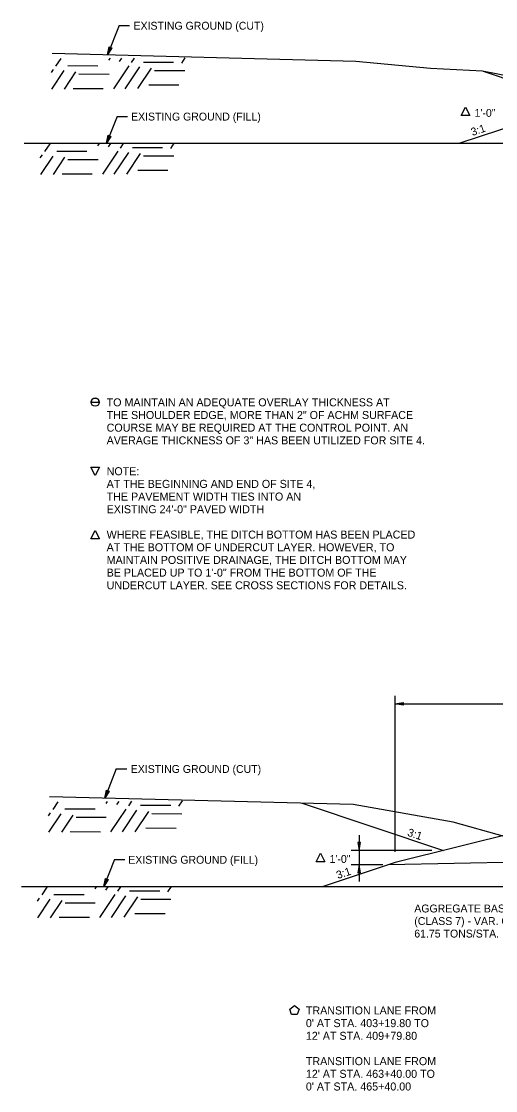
# Model space of a CAD drawing. Extents: x 1398565 to 1398920, y 1968324 to 1968581.
# Drawn here: x 1398765.9 to 1398801.5, y 1968324.3 to 1968404.5 of the extents above; entities that cross this region are included whole.
import ezdxf

# ---------------------------------------------------------------- set-up
doc = ezdxf.new("R2010")
doc.units = 0
for name, color, linetype in [('10', 7, 'Continuous'), ('19', 7, 'Continuous'), ('42', 7, 'Continuous'), ('9', 7, 'Continuous'), ('Default', 7, 'Continuous')]:
    doc.layers.add(name, color=color, linetype=linetype)

msp = doc.modelspace()

# ---------------------------------------------------------------- linework, layer by layer
at = {"layer": '10'}
msp.add_line((1398771.175, 1968375.948), (1398771.786, 1968375.948), dxfattribs=at)
for points in [[(1398799.247, 1968398.068), (1398799.568, 1968397.427), (1398798.927, 1968397.427)], [(1398771.163, 1968371.09), (1398771.804, 1968371.09), (1398771.484, 1968370.448)], [(1398771.484, 1968366.34), (1398771.804, 1968365.698), (1398771.163, 1968365.698)], [(1398788.375, 1968342.144), (1398788.695, 1968341.503), (1398788.054, 1968341.503)], [(1398786.069, 1968330.465), (1398786.418, 1968330.719), (1398786.768, 1968330.465), (1398786.634, 1968330.054), (1398786.202, 1968330.054)]]:
    msp.add_lwpolyline(points, close=True, dxfattribs=at)
msp.add_circle((1398771.48, 1968375.948), 0.306, dxfattribs=at)
msp.add_arc((1398771.48, 1968375.948), 0.306, 0, 180, dxfattribs=at)
at = {"layer": '19'}
for p, q in [((1398773.27, 1968404.183), (1398772.414, 1968401.981)), ((1398773.27, 1968404.183), (1398774.053, 1968404.183)), ((1398772.414, 1968401.981), (1398772.534, 1968402.578)), ((1398772.729, 1968402.502), (1398772.414, 1968401.981)), ((1398772.458, 1968402.135), (1398772.585, 1968402.558)), ((1398772.683, 1968402.52), (1398772.486, 1968402.125)), ((1398772.534, 1968402.578), (1398772.729, 1968402.502)), ((1398800.557, 1968400.762), (1398808.028, 1968398.272)), ((1398806.176, 1968397.808), (1398798.814, 1968395.354)), ((1398773.125, 1968397.374), (1398772.339, 1968395.354)), ((1398773.125, 1968397.374), (1398773.907, 1968397.374)), ((1398772.339, 1968395.354), (1398772.459, 1968395.952)), ((1398772.655, 1968395.876), (1398772.339, 1968395.354)), ((1398772.383, 1968395.509), (1398772.51, 1968395.932)), ((1398772.608, 1968395.894), (1398772.411, 1968395.498)), ((1398772.459, 1968395.952), (1398772.655, 1968395.876)), ((1398793.969, 1968342.234), (1398793.969, 1968353.935)), ((1398793.969, 1968353.335), (1398794.569, 1968353.44)), ((1398793.969, 1968353.335), (1398817.969, 1968353.335)), ((1398794.569, 1968353.23), (1398793.969, 1968353.335)), ((1398794.129, 1968353.35), (1398794.569, 1968353.385)), ((1398794.569, 1968353.28), (1398794.129, 1968353.32)), ((1398794.569, 1968353.44), (1398794.569, 1968353.23)), ((1398773.064, 1968348.472), (1398772.207, 1968346.271)), ((1398773.064, 1968348.472), (1398773.846, 1968348.472)), ((1398772.207, 1968346.271), (1398772.327, 1968346.868)), ((1398772.523, 1968346.792), (1398772.207, 1968346.271)), ((1398772.251, 1968346.425), (1398772.378, 1968346.848)), ((1398772.476, 1968346.81), (1398772.279, 1968346.414)), ((1398772.327, 1968346.868), (1398772.523, 1968346.792)), ((1398786.991, 1968345.885), (1398797.601, 1968342.348)), ((1398811.969, 1968345.94), (1398793.969, 1968341.44)), ((1398791.264, 1968343.506), (1398791.264, 1968342.23)), ((1398791.369, 1968342.948), (1398791.159, 1968342.948)), ((1398791.159, 1968342.948), (1398791.264, 1968342.348)), ((1398791.214, 1968342.948), (1398791.249, 1968342.508)), ((1398791.264, 1968342.348), (1398791.369, 1968342.948)), ((1398791.279, 1968342.508), (1398791.319, 1968342.948)), ((1398842.969, 1968342.264), (1398793.472, 1968341.274)), ((1398772.918, 1968341.664), (1398772.133, 1968339.644)), ((1398772.918, 1968341.664), (1398773.701, 1968341.664)), ((1398791.264, 1968342.23), (1398791.264, 1968340.024)), ((1398793.969, 1968341.44), (1398788.582, 1968339.644)), ((1398791.264, 1968341.274), (1398791.159, 1968340.674)), ((1398791.159, 1968340.674), (1398791.369, 1968340.674)), ((1398791.249, 1968341.114), (1398791.214, 1968340.674)), ((1398791.369, 1968340.674), (1398791.264, 1968341.274)), ((1398791.319, 1968340.674), (1398791.279, 1968341.114)), ((1398772.133, 1968339.644), (1398772.252, 1968340.241)), ((1398772.448, 1968340.165), (1398772.133, 1968339.644)), ((1398772.177, 1968339.799), (1398772.304, 1968340.222)), ((1398772.401, 1968340.183), (1398772.205, 1968339.788)), ((1398772.252, 1968340.241), (1398772.448, 1968340.165))]:
    msp.add_line(p, q, dxfattribs=at)
at = {"layer": '42'}
for points in [[(1398766.153, 1968395.354), (1398812.649, 1968395.354), (1398837.176, 1968401.464), (1398843.176, 1968401.704)], [(1398822.902, 1968397.908), (1398802.82, 1968400.302), (1398800.522, 1968400.764), (1398796.614, 1968400.956), (1398791.017, 1968401.495), (1398768.256, 1968402.089)], [(1398825.029, 1968342.779), (1398805.225, 1968342.765), (1398802.252, 1968343.377), (1398798.325, 1968344.462), (1398790.81, 1968345.785), (1398768.049, 1968346.379)], [(1398765.947, 1968339.644), (1398812.443, 1968339.644), (1398836.969, 1968345.753), (1398842.969, 1968345.993)]]:
    msp.add_lwpolyline(points, dxfattribs=at)
at = {"layer": '9'}
for p, q in [((1398768.53, 1968401.133), (1398768.919, 1968401.716)), ((1398772.514, 1968401.582), (1398772.617, 1968401.737)), ((1398773.312, 1968401.494), (1398773.477, 1968401.742)), ((1398774.202, 1968401.406), (1398774.429, 1968401.747)), ((1398777.966, 1968401.372), (1398778.23, 1968401.768)), ((1398768.193, 1968400.661), (1398768.346, 1968400.891)), ((1398768.221, 1968399.418), (1398769.144, 1968400.803)), ((1398769.42, 1968401.176), (1398771.682, 1968401.17)), ((1398772.871, 1968399.444), (1398774.018, 1968401.164)), ((1398773.731, 1968399.449), (1398774.816, 1968401.076)), ((1398774.684, 1968399.454), (1398775.706, 1968400.988)), ((1398775.092, 1968401.448), (1398777.354, 1968401.443)), ((1398775.93, 1968400.822), (1398778.192, 1968400.816)), ((1398769.173, 1968399.423), (1398770.035, 1968400.715)), ((1398770.258, 1968400.55), (1398772.52, 1968400.544)), ((1398769.819, 1968399.471), (1398772.081, 1968399.465)), ((1398775.491, 1968399.744), (1398777.753, 1968399.738)), ((1398767.705, 1968394.728), (1398768.093, 1968395.311)), ((1398771.688, 1968395.177), (1398771.791, 1968395.331)), ((1398772.486, 1968395.089), (1398772.651, 1968395.336)), ((1398773.377, 1968395.001), (1398773.604, 1968395.341)), ((1398777.14, 1968394.966), (1398777.405, 1968395.363)), ((1398767.367, 1968394.255), (1398767.521, 1968394.486)), ((1398767.395, 1968393.012), (1398768.318, 1968394.398)), ((1398768.594, 1968394.77), (1398770.856, 1968394.764)), ((1398772.046, 1968393.038), (1398773.192, 1968394.759)), ((1398772.906, 1968393.043), (1398773.99, 1968394.67)), ((1398773.858, 1968393.049), (1398774.881, 1968394.583)), ((1398774.266, 1968395.043), (1398776.528, 1968395.037)), ((1398775.104, 1968394.417), (1398777.366, 1968394.411)), ((1398768.347, 1968393.018), (1398769.209, 1968394.31)), ((1398769.432, 1968394.144), (1398771.694, 1968394.138)), ((1398768.993, 1968393.066), (1398771.255, 1968393.06)), ((1398774.665, 1968393.339), (1398776.927, 1968393.333)), ((1398768.324, 1968345.423), (1398768.712, 1968346.006)), ((1398772.308, 1968345.872), (1398772.41, 1968346.027)), ((1398773.105, 1968345.784), (1398773.27, 1968346.031)), ((1398773.996, 1968345.696), (1398774.223, 1968346.037)), ((1398774.885, 1968345.738), (1398777.147, 1968345.732)), ((1398777.76, 1968345.662), (1398778.024, 1968346.058)), ((1398767.986, 1968344.95), (1398768.14, 1968345.181)), ((1398768.014, 1968343.708), (1398768.938, 1968345.093)), ((1398768.967, 1968343.713), (1398769.828, 1968345.005)), ((1398769.214, 1968345.465), (1398771.476, 1968345.459)), ((1398770.051, 1968344.839), (1398772.313, 1968344.833)), ((1398772.665, 1968343.734), (1398773.812, 1968345.454)), ((1398773.525, 1968343.738), (1398774.609, 1968345.366)), ((1398774.477, 1968343.744), (1398775.5, 1968345.278)), ((1398775.723, 1968345.112), (1398777.985, 1968345.106)), ((1398775.284, 1968344.034), (1398777.546, 1968344.028)), ((1398769.612, 1968343.761), (1398771.874, 1968343.755)), ((1398767.498, 1968339.018), (1398767.886, 1968339.6)), ((1398768.388, 1968339.06), (1398770.65, 1968339.054)), ((1398771.482, 1968339.467), (1398771.585, 1968339.621)), ((1398772.28, 1968339.378), (1398772.445, 1968339.626)), ((1398773.17, 1968339.291), (1398773.397, 1968339.631)), ((1398774.06, 1968339.333), (1398776.322, 1968339.327)), ((1398776.934, 1968339.256), (1398777.198, 1968339.652)), ((1398767.16, 1968338.545), (1398767.314, 1968338.776)), ((1398767.188, 1968337.302), (1398768.112, 1968338.687)), ((1398768.141, 1968337.307), (1398769.002, 1968338.6)), ((1398769.226, 1968338.434), (1398771.488, 1968338.428)), ((1398771.839, 1968337.328), (1398772.986, 1968339.048)), ((1398772.699, 1968337.333), (1398773.784, 1968338.96)), ((1398773.651, 1968337.338), (1398774.674, 1968338.872)), ((1398774.897, 1968338.707), (1398777.159, 1968338.701)), ((1398774.458, 1968337.629), (1398776.72, 1968337.623)), ((1398768.787, 1968337.356), (1398771.049, 1968337.35))]:
    msp.add_line(p, q, dxfattribs=at)
at = {"layer": 'Default'}
for p, q in [((1398796.713, 1968342.348), (1398790.669, 1968342.348)), ((1398793.036, 1968341.274), (1398790.683, 1968341.274))]:
    msp.add_line(p, q, dxfattribs=at)

# ---------------------------------------------------------------- texts
at = {"layer": '10'}
for s, height, rotation, p in [('EXISTING GROUND (CUT)', 0.59001, 360, (1398774.354, 1968403.872)), ('EXISTING GROUND (FILL)', 0.59001, 360, (1398774.167, 1968397.063)), ('1\'-0"', 0.59, 360, (1398799.922, 1968397.34)), ('3:1', 0.59, 18.49392, (1398799.763, 1968395.897)), ('EXISTING GROUND (CUT)', 0.59001, 360, (1398774.148, 1968348.161)), ('3:1', 0.59, 341.52236, (1398794.842, 1968343.463)), ('EXISTING GROUND (FILL)', 0.59001, 360, (1398773.96, 1968341.353)), ('1\'-0"', 0.59, 360, (1398789.049, 1968341.417)), ('3:1', 0.59, 18.49392, (1398789.671, 1968340.202))]:
    msp.add_text(s, height=height, rotation=rotation, dxfattribs=at).set_placement(p)
at = {"layer": '19'}
for s, p in [('AGGREGATE BASE COURSE', (1398795.403, 1968337.703)), ('(CLASS 7) - VAR. COMPACTED DEPTH', (1398795.403, 1968336.763)), ('61.75 TONS/STA.', (1398795.403, 1968335.823))]:
    msp.add_text(s, height=0.59001, rotation=360, dxfattribs=at).set_placement(p)
at = {"layer": '42'}
for s, p in [('TO MAINTAIN AN ADEQUATE OVERLAY THICKNESS AT', (1398772.339, 1968375.639)), ('THE SHOULDER EDGE, MORE THAN 2" OF ACHM SURFACE', (1398772.339, 1968374.689)), ('COURSE MAY BE REQUIRED AT THE CONTROL POINT. AN', (1398772.339, 1968373.739)), ('AVERAGE THICKNESS OF 3" HAS BEEN UTILIZED FOR SITE 4.', (1398772.339, 1968372.789)), ('NOTE:', (1398772.339, 1968370.475)), ('AT THE BEGINNING AND END OF SITE 4,', (1398772.339, 1968369.525)), ('THE PAVEMENT WIDTH TIES INTO AN', (1398772.339, 1968368.575)), ('EXISTING 24\'-0" PAVED WIDTH', (1398772.339, 1968367.625)), ('WHERE FEASIBLE, THE DITCH BOTTOM HAS BEEN PLACED', (1398772.339, 1968365.725)), ('AT THE BOTTOM OF UNDERCUT LAYER. HOWEVER, TO', (1398772.339, 1968364.775)), ('MAINTAIN POSITIVE DRAINAGE, THE DITCH BOTTOM MAY', (1398772.339, 1968363.825)), ('BE PLACED UP TO 1\'-0" FROM THE BOTTOM OF THE', (1398772.339, 1968362.875)), ('UNDERCUT LAYER. SEE CROSS SECTIONS FOR DETAILS.', (1398772.339, 1968361.925)), ('TRANSITION LANE FROM', (1398787.276, 1968330.056)), ("0' AT STA. 403+19.80 TO", (1398787.276, 1968329.106)), ("12' AT STA. 409+79.80", (1398787.276, 1968328.156)), ('TRANSITION LANE FROM', (1398787.276, 1968326.256)), ("12' AT STA. 463+40.00 TO", (1398787.276, 1968325.306)), ("0' AT STA. 465+40.00", (1398787.276, 1968324.356))]:
    msp.add_text(s, height=0.6, dxfattribs=at).set_placement(p)

doc.saveas('drawing.dxf')
